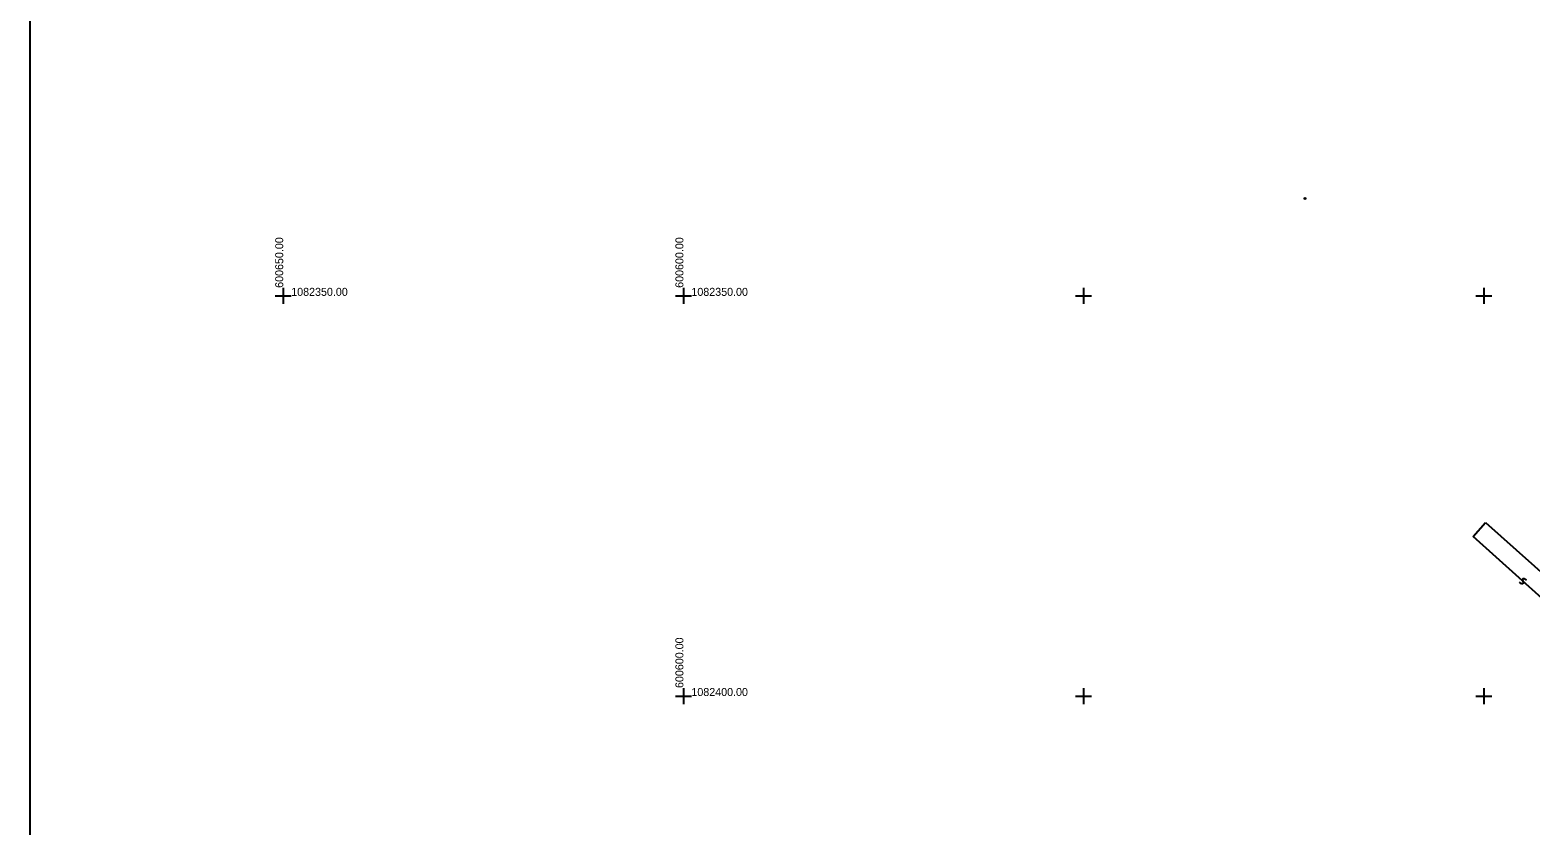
# Model space of a CAD drawing. Extents: x -601196 to -600262, y -1082523 to -1081922.
# Drawn here: x -600681.6 to -600494.1, y -1082416.2 to -1082316.8 of the extents above; entities that cross this region are included whole.
import ezdxf

# ---------------------------------------------------------------- set-up
doc = ezdxf.new("R2010")
doc.units = 0
for name, color, linetype in [('Vrstva 47', 7, 'Continuous'), ('Vrstva 59', 7, 'Continuous'), ('Vrstva 61', 7, 'Continuous'), ('Vrstva 63', 7, 'Continuous')]:
    doc.layers.add(name, color=color, linetype=linetype)

msp = doc.modelspace()

# ---------------------------------------------------------------- linework, layer by layer
at = {"layer": 'Vrstva 47'}
for p, q in [((-600522.41, -1082337.77), (-600522.26, -1082337.77)), ((-600522.41, -1082337.92), (-600522.41, -1082337.77)), ((-600522.26, -1082337.92), (-600522.41, -1082337.92)), ((-600522.26, -1082337.77), (-600522.26, -1082337.92)), ((-600501.32, -1082380.05), (-600499.79, -1082378.34)), ((-600499.79, -1082378.34), (-600474.85, -1082400.54)), ((-600488.87, -1082391.28), (-600501.32, -1082380.05)), ((-600495.26, -1082385.99), (-600495.55, -1082385.79)), ((-600495.11, -1082385.98), (-600495.26, -1082385.99)), ((-600495.08, -1082385.34), (-600495.14, -1082385.42)), ((-600495.14, -1082385.42), (-600495.14, -1082385.56)), ((-600495.14, -1082385.56), (-600495.05, -1082385.77)), ((-600495.05, -1082385.91), (-600495.11, -1082385.98)), ((-600494.93, -1082385.34), (-600495.08, -1082385.34)), ((-600495.05, -1082385.77), (-600495.05, -1082385.91)), ((-600494.64, -1082385.53), (-600494.93, -1082385.34))]:
    msp.add_line(p, q, dxfattribs=at)
at = {"layer": 'Vrstva 59'}
msp.add_lwpolyline([(-600681.64, -1082515.69), (-600681.64, -1081921.69), (-600261.64, -1081921.69), (-600261.64, -1082515.69)], close=True, dxfattribs=at)
at = {"layer": 'Vrstva 61'}
for p, q in [((-600650, -1082349), (-600650, -1082351)), ((-600600, -1082349), (-600600, -1082351)), ((-600600, -1082349), (-600600, -1082351)), ((-600550, -1082349), (-600550, -1082351)), ((-600550, -1082349), (-600550, -1082351)), ((-600500, -1082349), (-600500, -1082351)), ((-600500, -1082349), (-600500, -1082351)), ((-600651, -1082350), (-600649, -1082350)), ((-600601, -1082350), (-600599, -1082350)), ((-600601, -1082350), (-600599, -1082350)), ((-600551, -1082350), (-600549, -1082350)), ((-600551, -1082350), (-600549, -1082350)), ((-600501, -1082350), (-600499, -1082350)), ((-600501, -1082350), (-600499, -1082350)), ((-600601, -1082400), (-600599, -1082400)), ((-600600, -1082399), (-600600, -1082401)), ((-600551, -1082400), (-600549, -1082400)), ((-600550, -1082399), (-600550, -1082401)), ((-600501, -1082400), (-600499, -1082400)), ((-600500, -1082399), (-600500, -1082401))]:
    msp.add_line(p, q, dxfattribs=at)

# ---------------------------------------------------------------- texts
at = {"layer": 'Vrstva 63'}
for s, p in [('600650.00', (-600650, -1082349)), ('600600.00', (-600600, -1082349)), ('600600.00', (-600600, -1082399))]:
    msp.add_text(s, height=1, rotation=90, dxfattribs=at).set_placement(p)
for s, p in [('1082350.00', (-600649, -1082350)), ('1082350.00', (-600599, -1082350)), ('1082400.00', (-600599, -1082400))]:
    msp.add_text(s, height=1, dxfattribs=at).set_placement(p)

doc.saveas('drawing.dxf')
